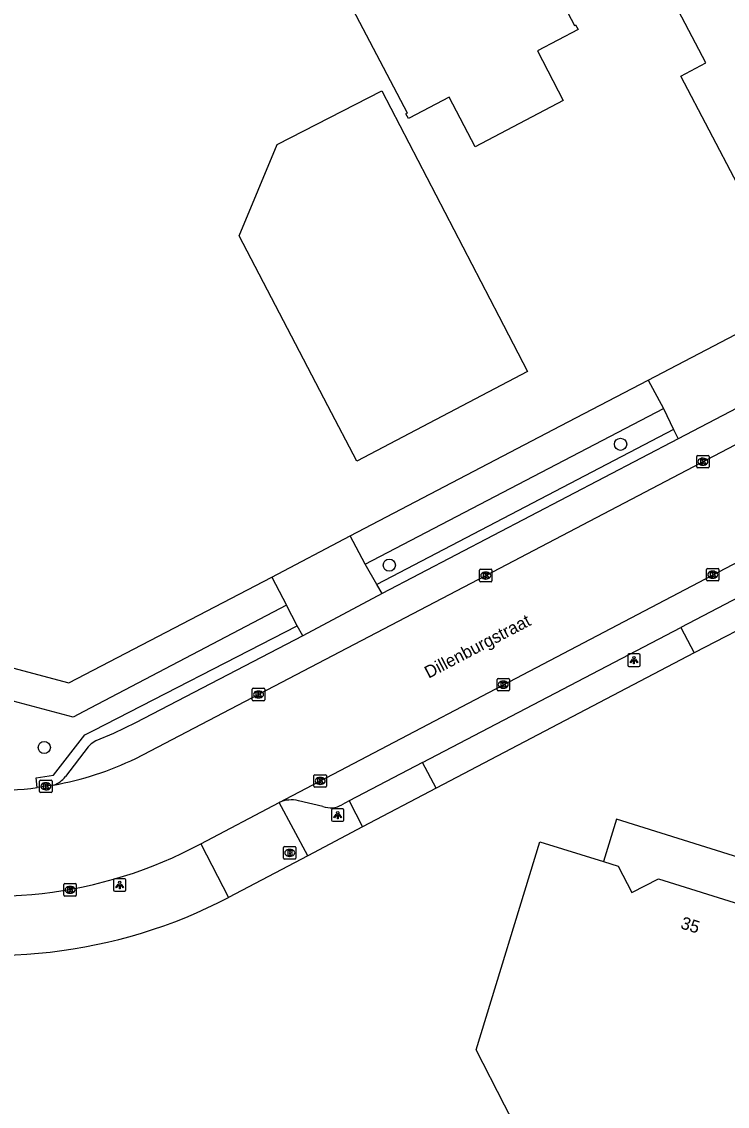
# Model space of a CAD drawing. Extents: x 157692 to 159670, y 381454 to 383289.
# Drawn here: x 158266.5 to 158323.1, y 381791.8 to 381878.9 of the extents above; entities that cross this region are included whole.
import ezdxf

# ---------------------------------------------------------------- set-up
doc = ezdxf.new("R2010")
doc.units = 0
for name, color, linetype in [('IMGEO_Boom', 7, 'Continuous'), ('IMGEO_Brandkraan', 7, 'Continuous'), ('IMGEO_Kolk', 7, 'Continuous'), ('IMGEO_Lichtpunt', 7, 'Continuous'), ('IMGEO_Openbare_ruimte_label', 7, 'Continuous'), ('IMGEO_Pand', 7, 'Continuous'), ('IMGEO_Pand_nummerreeks', 7, 'Continuous'), ('IMGEO_Pand_overbouw', 7, 'Continuous'), ('IMGEO_Rijbaan_lokaal_gesloten', 7, 'Continuous'), ('IMGEO_Rijbaan_lokaal_open', 7, 'Continuous'), ('IMGEO_Voetpad_open', 7, 'Continuous')]:
    doc.layers.add(name, color=color, linetype=linetype)

msp = doc.modelspace()

# ---------------------------------------------------------------- linework, layer by layer
at = {"layer": 'IMGEO_Boom'}
for centre in [(158314.56, 381844.953), (158295.991, 381835.243), (158268.292, 381820.598)]:
    msp.add_circle(centre, 0.489, dxfattribs=at)
at = {"layer": 'IMGEO_Brandkraan'}
for p, q in [((158287.494, 381811.713), (158287.494, 381812.565)), ((158287.569, 381812.639), (158288.421, 381812.639)), ((158288.005, 381811.859), (158287.98, 381811.859)), ((158287.982, 381812.419), (158288.007, 381812.419)), ((158288.495, 381812.565), (158288.495, 381811.713)), ((158288.421, 381811.639), (158287.569, 381811.639))]:
    msp.add_line(p, q, dxfattribs=at)
for points in [[(158287.494, 381811.713), (158287.494, 381812.565)], [(158287.569, 381812.639), (158288.421, 381812.639)], [(158287.842, 381812.339), (158287.842, 381811.939), (158288.055, 381811.939)], [(158288.073, 381812.339), (158287.842, 381812.339)], [(158288.021, 381812.258), (158287.967, 381812.258), (158287.967, 381812.182)], [(158287.967, 381812.182), (158288.02, 381812.182)], [(158288.029, 381812.106), (158287.967, 381812.106), (158287.967, 381812.025)], [(158287.967, 381812.025), (158288.029, 381812.025)], [(158288.495, 381812.565), (158288.495, 381811.713)], [(158288.421, 381811.639), (158287.569, 381811.639)]]:
    msp.add_lwpolyline(points, dxfattribs=at)
for centre, radius, start, end in [((158287.571, 381812.563), 0.0765, 91.55205, 178.44795), ((158287.571, 381812.563), 0.0765, 91.55205, 178.44795), ((158288.022, 381812.22), 0.0379, 267.82845, 90.93552), ((158288.03, 381812.065), 0.0404, 269.87594, 90.50774), ((158288.061, 381812.19), 0.251, 268.66757, 293.53466), ((158288.077, 381812.194), 0.145, 59.4692, 91.53667), ((158288.102, 381812.241), 0.0922, 285.51372, 58.15012), ((158288.107, 381812.049), 0.105, 301.31148, 78.98903), ((158288.419, 381812.563), 0.0765, 1.55205, 88.44795), ((158288.419, 381812.563), 0.0765, 1.55205, 88.44795), ((158287.571, 381811.715), 0.0765, 181.55205, 268.44795), ((158287.571, 381811.715), 0.0765, 181.55205, 268.44795), ((158288.419, 381811.715), 0.0765, 271.55205, 358.44795), ((158288.419, 381811.715), 0.0765, 271.55205, 358.44795)]:
    msp.add_arc(centre, radius, start, end, dxfattribs=at)
for centre, major_axis, ratio, start_param, end_param in [((158287.981, 381812.139), (-0.387, 0.002), 0.722429, 4.712389, 7.853982), ((158288.006, 381812.139), (-0.39, 0.002), 0.717154, 1.570796, 4.712389)]:
    msp.add_ellipse(centre, major_axis=major_axis, ratio=ratio, start_param=start_param, end_param=end_param, dxfattribs=at)
at = {"layer": 'IMGEO_Kolk'}
for p, q in [((158320.743, 381844.055), (158321.595, 381844.055)), ((158320.668, 381843.129), (158320.668, 381843.981)), ((158321.179, 381843.275), (158321.154, 381843.275)), ((158321.156, 381843.835), (158321.181, 381843.835)), ((158321.669, 381843.981), (158321.669, 381843.129)), ((158321.595, 381843.055), (158320.743, 381843.055)), ((158303.233, 381833.986), (158303.233, 381834.838)), ((158303.308, 381834.912), (158304.16, 381834.912)), ((158303.721, 381834.692), (158303.746, 381834.692)), ((158304.234, 381834.838), (158304.234, 381833.986)), ((158321.455, 381834.055), (158321.455, 381834.907)), ((158321.53, 381834.981), (158322.382, 381834.981)), ((158321.943, 381834.761), (158321.968, 381834.761)), ((158322.456, 381834.907), (158322.456, 381834.055)), ((158304.16, 381833.912), (158303.308, 381833.912)), ((158303.744, 381834.132), (158303.719, 381834.132)), ((158322.382, 381833.981), (158321.53, 381833.981)), ((158321.966, 381834.201), (158321.941, 381834.201)), ((158304.644, 381825.222), (158304.644, 381826.074)), ((158304.719, 381826.148), (158305.571, 381826.148)), ((158305.132, 381825.928), (158305.157, 381825.928)), ((158305.645, 381826.074), (158305.645, 381825.222)), ((158284.993, 381824.433), (158284.993, 381825.285)), ((158285.068, 381825.359), (158285.92, 381825.359)), ((158285.481, 381825.139), (158285.506, 381825.139)), ((158285.994, 381825.285), (158285.994, 381824.433)), ((158305.571, 381825.148), (158304.719, 381825.148)), ((158305.155, 381825.368), (158305.13, 381825.368)), ((158285.92, 381824.359), (158285.068, 381824.359)), ((158285.504, 381824.579), (158285.479, 381824.579)), ((158267.992, 381817.984), (158268.844, 381817.984)), ((158289.941, 381817.488), (158289.941, 381818.34)), ((158290.016, 381818.414), (158290.868, 381818.414)), ((158290.429, 381818.194), (158290.454, 381818.194)), ((158290.942, 381818.34), (158290.942, 381817.488)), ((158267.917, 381817.058), (158267.917, 381817.91)), ((158268.428, 381817.204), (158268.403, 381817.204)), ((158268.405, 381817.764), (158268.43, 381817.764)), ((158268.918, 381817.91), (158268.918, 381817.058)), ((158290.868, 381817.414), (158290.016, 381817.414)), ((158290.452, 381817.634), (158290.427, 381817.634)), ((158268.844, 381816.984), (158267.992, 381816.984)), ((158269.863, 381808.743), (158269.863, 381809.595)), ((158269.938, 381809.669), (158270.79, 381809.669)), ((158270.351, 381809.449), (158270.376, 381809.449)), ((158270.864, 381809.595), (158270.864, 381808.743)), ((158270.79, 381808.669), (158269.938, 381808.669)), ((158270.374, 381808.889), (158270.349, 381808.889))]:
    msp.add_line(p, q, dxfattribs=at)
for points in [[(158320.743, 381844.055), (158321.595, 381844.055)], [(158320.668, 381843.129), (158320.668, 381843.981)], [(158320.989, 381843.755), (158321.112, 381843.755), (158321.112, 381843.604), (158321.242, 381843.755), (158321.406, 381843.755), (158321.26, 381843.604), (158321.413, 381843.355), (158321.261, 381843.355), (158321.176, 381843.519), (158321.112, 381843.452), (158321.112, 381843.355), (158320.989, 381843.355), (158320.989, 381843.755)], [(158321.669, 381843.981), (158321.669, 381843.129)], [(158321.595, 381843.055), (158320.743, 381843.055)], [(158303.233, 381833.986), (158303.233, 381834.838)], [(158303.308, 381834.912), (158304.16, 381834.912)], [(158303.554, 381834.612), (158303.677, 381834.612), (158303.677, 381834.461), (158303.807, 381834.612), (158303.971, 381834.612), (158303.825, 381834.461), (158303.978, 381834.212), (158303.826, 381834.212), (158303.741, 381834.376), (158303.677, 381834.309), (158303.677, 381834.212), (158303.554, 381834.212), (158303.554, 381834.612)], [(158304.234, 381834.838), (158304.234, 381833.986)], [(158321.455, 381834.055), (158321.455, 381834.907)], [(158321.53, 381834.981), (158322.382, 381834.981)], [(158321.776, 381834.681), (158321.899, 381834.681), (158321.899, 381834.53), (158322.029, 381834.681), (158322.193, 381834.681), (158322.047, 381834.53), (158322.2, 381834.281), (158322.048, 381834.281), (158321.963, 381834.445), (158321.899, 381834.378), (158321.899, 381834.281), (158321.776, 381834.281), (158321.776, 381834.681)], [(158322.456, 381834.907), (158322.456, 381834.055)], [(158304.16, 381833.912), (158303.308, 381833.912)], [(158322.382, 381833.981), (158321.53, 381833.981)], [(158304.644, 381825.222), (158304.644, 381826.074)], [(158304.719, 381826.148), (158305.571, 381826.148)], [(158304.965, 381825.848), (158305.088, 381825.848), (158305.088, 381825.697), (158305.218, 381825.848), (158305.382, 381825.848), (158305.236, 381825.697), (158305.389, 381825.448), (158305.237, 381825.448), (158305.152, 381825.612), (158305.088, 381825.545), (158305.088, 381825.448), (158304.965, 381825.448), (158304.965, 381825.848)], [(158305.645, 381826.074), (158305.645, 381825.222)], [(158284.993, 381824.433), (158284.993, 381825.285)], [(158285.068, 381825.359), (158285.92, 381825.359)], [(158285.314, 381825.059), (158285.437, 381825.059), (158285.437, 381824.908), (158285.567, 381825.059), (158285.731, 381825.059), (158285.585, 381824.908), (158285.738, 381824.659), (158285.586, 381824.659), (158285.501, 381824.823), (158285.437, 381824.756), (158285.437, 381824.659), (158285.314, 381824.659), (158285.314, 381825.059)], [(158285.994, 381825.285), (158285.994, 381824.433)], [(158305.571, 381825.148), (158304.719, 381825.148)], [(158285.92, 381824.359), (158285.068, 381824.359)], [(158267.992, 381817.984), (158268.844, 381817.984)], [(158289.941, 381817.488), (158289.941, 381818.34)], [(158290.016, 381818.414), (158290.868, 381818.414)], [(158290.262, 381818.114), (158290.385, 381818.114), (158290.385, 381817.963), (158290.515, 381818.114), (158290.679, 381818.114), (158290.533, 381817.963), (158290.686, 381817.714), (158290.534, 381817.714), (158290.449, 381817.878), (158290.385, 381817.811), (158290.385, 381817.714), (158290.262, 381817.714), (158290.262, 381818.114)], [(158290.942, 381818.34), (158290.942, 381817.488)], [(158267.917, 381817.058), (158267.917, 381817.91)], [(158268.238, 381817.684), (158268.361, 381817.684), (158268.361, 381817.533), (158268.491, 381817.684), (158268.655, 381817.684), (158268.509, 381817.533), (158268.662, 381817.284), (158268.51, 381817.284), (158268.425, 381817.448), (158268.361, 381817.381), (158268.361, 381817.284), (158268.238, 381817.284), (158268.238, 381817.684)], [(158268.918, 381817.91), (158268.918, 381817.058)], [(158290.868, 381817.414), (158290.016, 381817.414)], [(158268.844, 381816.984), (158267.992, 381816.984)], [(158269.863, 381808.743), (158269.863, 381809.595)], [(158269.938, 381809.669), (158270.79, 381809.669)], [(158270.184, 381809.369), (158270.307, 381809.369), (158270.307, 381809.218), (158270.437, 381809.369), (158270.601, 381809.369), (158270.455, 381809.218), (158270.608, 381808.969), (158270.456, 381808.969), (158270.371, 381809.133), (158270.307, 381809.066), (158270.307, 381808.969), (158270.184, 381808.969), (158270.184, 381809.369)], [(158270.864, 381809.595), (158270.864, 381808.743)], [(158270.79, 381808.669), (158269.938, 381808.669)]]:
    msp.add_lwpolyline(points, dxfattribs=at)
for centre, start, end in [((158320.745, 381843.979), 91.55205, 178.44795), ((158320.745, 381843.979), 91.55205, 178.44795), ((158321.593, 381843.979), 1.55205, 88.44795), ((158321.593, 381843.979), 1.55205, 88.44795), ((158320.745, 381843.131), 181.55205, 268.44795), ((158320.745, 381843.131), 181.55205, 268.44795), ((158321.593, 381843.131), 271.55205, 358.44795), ((158321.593, 381843.131), 271.55205, 358.44795), ((158303.31, 381834.836), 91.55205, 178.44795), ((158303.31, 381834.836), 91.55205, 178.44795), ((158304.158, 381834.836), 1.55205, 88.44795), ((158304.158, 381834.836), 1.55205, 88.44795), ((158321.532, 381834.905), 91.55205, 178.44795), ((158321.532, 381834.905), 91.55205, 178.44795), ((158322.38, 381834.905), 1.55205, 88.44795), ((158322.38, 381834.905), 1.55205, 88.44795), ((158303.31, 381833.988), 181.55205, 268.44795), ((158303.31, 381833.988), 181.55205, 268.44795), ((158304.158, 381833.988), 271.55205, 358.44795), ((158304.158, 381833.988), 271.55205, 358.44795), ((158321.532, 381834.057), 181.55205, 268.44795), ((158321.532, 381834.057), 181.55205, 268.44795), ((158322.38, 381834.057), 271.55205, 358.44795), ((158322.38, 381834.057), 271.55205, 358.44795), ((158304.721, 381826.072), 91.55205, 178.44795), ((158304.721, 381826.072), 91.55205, 178.44795), ((158305.569, 381826.072), 1.55205, 88.44795), ((158305.569, 381826.072), 1.55205, 88.44795), ((158285.07, 381825.283), 91.55205, 178.44795), ((158285.07, 381825.283), 91.55205, 178.44795), ((158285.918, 381825.283), 1.55205, 88.44795), ((158285.918, 381825.283), 1.55205, 88.44795), ((158304.721, 381825.224), 181.55205, 268.44795), ((158304.721, 381825.224), 181.55205, 268.44795), ((158305.569, 381825.224), 271.55205, 358.44795), ((158305.569, 381825.224), 271.55205, 358.44795), ((158285.07, 381824.435), 181.55205, 268.44795), ((158285.07, 381824.435), 181.55205, 268.44795), ((158285.918, 381824.435), 271.55205, 358.44795), ((158285.918, 381824.435), 271.55205, 358.44795), ((158267.994, 381817.908), 91.55205, 178.44795), ((158267.994, 381817.908), 91.55205, 178.44795), ((158268.842, 381817.908), 1.55205, 88.44795), ((158268.842, 381817.908), 1.55205, 88.44795), ((158290.018, 381818.338), 91.55205, 178.44795), ((158290.018, 381818.338), 91.55205, 178.44795), ((158290.866, 381818.338), 1.55205, 88.44795), ((158290.866, 381818.338), 1.55205, 88.44795), ((158267.994, 381817.06), 181.55205, 268.44795), ((158267.994, 381817.06), 181.55205, 268.44795), ((158268.842, 381817.06), 271.55205, 358.44795), ((158268.842, 381817.06), 271.55205, 358.44795), ((158290.018, 381817.49), 181.55205, 268.44795), ((158290.018, 381817.49), 181.55205, 268.44795), ((158290.866, 381817.49), 271.55205, 358.44795), ((158290.866, 381817.49), 271.55205, 358.44795), ((158269.94, 381809.593), 91.55205, 178.44795), ((158269.94, 381809.593), 91.55205, 178.44795), ((158270.788, 381809.593), 1.55205, 88.44795), ((158270.788, 381809.593), 1.55205, 88.44795), ((158269.94, 381808.745), 181.55205, 268.44795), ((158269.94, 381808.745), 181.55205, 268.44795), ((158270.788, 381808.745), 271.55205, 358.44795), ((158270.788, 381808.745), 271.55205, 358.44795)]:
    msp.add_arc(centre, 0.0765, start, end, dxfattribs=at)
for centre, major_axis, ratio, start_param, end_param in [((158321.155, 381843.555), (-0.387, 0.002), 0.722429, 4.712389, 7.853982), ((158321.18, 381843.555), (-0.39, 0.002), 0.717154, 1.570796, 4.712389), ((158303.72, 381834.412), (-0.387, 0.002), 0.722429, 4.712389, 7.853982), ((158303.745, 381834.412), (-0.39, 0.002), 0.717154, 1.570796, 4.712389), ((158321.942, 381834.481), (-0.387, 0.002), 0.722429, 4.712389, 7.853982), ((158321.967, 381834.481), (-0.39, 0.002), 0.717154, 1.570796, 4.712389), ((158305.131, 381825.648), (-0.387, 0.002), 0.722429, 4.712389, 7.853982), ((158305.156, 381825.648), (-0.39, 0.002), 0.717154, 1.570796, 4.712389), ((158285.48, 381824.859), (-0.387, 0.002), 0.722429, 4.712389, 7.853982), ((158285.505, 381824.859), (-0.39, 0.002), 0.717154, 1.570796, 4.712389), ((158290.428, 381817.914), (-0.387, 0.002), 0.722429, 4.712389, 7.853982), ((158290.453, 381817.914), (-0.39, 0.002), 0.717154, 1.570796, 4.712389), ((158268.404, 381817.484), (-0.387, 0.002), 0.722429, 4.712389, 7.853982), ((158268.429, 381817.484), (-0.39, 0.002), 0.717154, 1.570796, 4.712389), ((158270.35, 381809.169), (-0.387, 0.002), 0.722429, 4.712389, 7.853982), ((158270.375, 381809.169), (-0.39, 0.002), 0.717154, 1.570796, 4.712389)]:
    msp.add_ellipse(centre, major_axis=major_axis, ratio=ratio, start_param=start_param, end_param=end_param, dxfattribs=at)
at = {"layer": 'IMGEO_Lichtpunt'}
for p, q in [((158315.132, 381828.019), (158315.132, 381827.212)), ((158315.132, 381828.019), (158315.132, 381827.212)), ((158316.034, 381828.114), (158315.226, 381828.114)), ((158316.034, 381828.114), (158315.226, 381828.114)), ((158316.128, 381827.212), (158316.128, 381828.019)), ((158316.128, 381827.212), (158316.128, 381828.019)), ((158315.226, 381827.118), (158316.034, 381827.118)), ((158315.226, 381827.118), (158316.034, 381827.118)), ((158291.355, 381815.576), (158291.355, 381814.769)), ((158291.355, 381815.576), (158291.355, 381814.769)), ((158292.257, 381815.671), (158291.449, 381815.671)), ((158292.257, 381815.671), (158291.449, 381815.671)), ((158292.351, 381814.769), (158292.351, 381815.576)), ((158292.351, 381814.769), (158292.351, 381815.576)), ((158291.449, 381814.675), (158292.257, 381814.675)), ((158291.449, 381814.675), (158292.257, 381814.675)), ((158273.851, 381809.967), (158273.851, 381809.16)), ((158273.851, 381809.967), (158273.851, 381809.16)), ((158274.753, 381810.062), (158273.945, 381810.062)), ((158274.753, 381810.062), (158273.945, 381810.062)), ((158274.847, 381809.16), (158274.847, 381809.967)), ((158274.847, 381809.16), (158274.847, 381809.967)), ((158273.945, 381809.066), (158274.753, 381809.066)), ((158273.945, 381809.066), (158274.753, 381809.066))]:
    msp.add_line(p, q, dxfattribs=at)
for points in [[(158315.506, 381827.683), (158315.545, 381827.655), (158315.357, 381827.393), (158315.319, 381827.42), (158315.506, 381827.683)], [(158315.608, 381827.635), (158315.655, 381827.635), (158315.655, 381827.313), (158315.608, 381827.313), (158315.608, 381827.635)], [(158315.718, 381827.655), (158315.756, 381827.682), (158315.943, 381827.42), (158315.904, 381827.392), (158315.718, 381827.655)], [(158291.729, 381815.24), (158291.768, 381815.212), (158291.58, 381814.95), (158291.542, 381814.977), (158291.729, 381815.24)], [(158291.831, 381815.192), (158291.878, 381815.192), (158291.878, 381814.87), (158291.831, 381814.87), (158291.831, 381815.192)], [(158291.941, 381815.212), (158291.979, 381815.239), (158292.166, 381814.977), (158292.127, 381814.949), (158291.941, 381815.212)], [(158274.225, 381809.631), (158274.264, 381809.603), (158274.076, 381809.341), (158274.038, 381809.368), (158274.225, 381809.631)], [(158274.327, 381809.583), (158274.374, 381809.583), (158274.374, 381809.261), (158274.327, 381809.261), (158274.327, 381809.583)], [(158274.437, 381809.603), (158274.475, 381809.63), (158274.662, 381809.368), (158274.623, 381809.34), (158274.437, 381809.603)]]:
    msp.add_lwpolyline(points, dxfattribs=at)
for centre in [(158315.631, 381827.817), (158291.854, 381815.374), (158274.35, 381809.765)]:
    msp.add_circle(centre, 0.0994, dxfattribs=at)
for centre, start, end in [((158315.226, 381828.019), 90, 180), ((158315.226, 381828.019), 90, 180), ((158316.034, 381828.019), 0, 90), ((158316.034, 381828.019), 0, 90), ((158315.226, 381827.212), 180, 270), ((158315.226, 381827.212), 180, 270), ((158316.034, 381827.212), 270, 0), ((158316.034, 381827.212), 270, 360), ((158291.449, 381815.576), 90, 180), ((158291.449, 381815.576), 90, 180), ((158292.257, 381815.576), 0, 90), ((158292.257, 381815.576), 0, 90), ((158291.449, 381814.769), 180, 270), ((158291.449, 381814.769), 180, 270), ((158292.257, 381814.769), 270, 0), ((158292.257, 381814.769), 270, 360), ((158273.945, 381809.967), 90, 180), ((158273.945, 381809.967), 90, 180), ((158274.753, 381809.967), 0, 90), ((158274.753, 381809.967), 0, 90), ((158273.945, 381809.16), 180, 270), ((158273.945, 381809.16), 180, 270), ((158274.753, 381809.16), 270, 0), ((158274.753, 381809.16), 270, 360)]:
    msp.add_arc(centre, 0.0946, start, end, dxfattribs=at)
at = {"layer": 'IMGEO_Pand'}
for points in [[(158333.425, 381881.552), (158340.173, 381868.726), (158333.445, 381865.185), (158333.06, 381865.918), (158331.024, 381864.849), (158331.41, 381864.114), (158326.268, 381861.408), (158323.944, 381865.836), (158319.391, 381874.508), (158321.413, 381875.583), (158309.292, 381898.698)], [(158302.242, 381895.001), (158310.853, 381878.582), (158310.95, 381878.633), (158311.145, 381878.261), (158307.877, 381876.547), (158309.962, 381872.571), (158302.877, 381868.855), (158300.792, 381872.832), (158297.598, 381871.157), (158297.524, 381871.118), (158297.329, 381871.49), (158297.444, 381871.55), (158288.402, 381888.793)], [(158304.778, 381855.232), (158307.082, 381850.794), (158293.376, 381843.602), (158291.065, 381848.036), (158283.944, 381861.695), (158286.984, 381869.041), (158295.379, 381873.333), (158304.778, 381855.232)], [(158323.96, 381772.543), (158314.42, 381790.731), (158307.678, 381787.188), (158305.25, 381791.883), (158302.954, 381796.324), (158308.072, 381813.038), (158313.184, 381811.438), (158314.365, 381811.069), (158315.463, 381808.959), (158317.611, 381810.064), (158324.541, 381807.889), (158329.01, 381810.217), (158332.059, 381811.805), (158334.384, 381807.379), (158362.682, 381753.509), (158364.526, 381750), (158365.008, 381749.083), (158325.61, 381728.481), (158323.288, 381732.91), (158314.326, 381750), (158309.193, 381759.788), (158311.05, 381765.753), (158323.96, 381772.543)]]:
    msp.add_lwpolyline(points, dxfattribs=at)
at = {"layer": 'IMGEO_Pand_overbouw'}
msp.add_lwpolyline([(158329.01, 381810.217), (158314.225, 381814.834), (158313.184, 381811.438), (158314.365, 381811.069), (158315.463, 381808.959), (158317.611, 381810.064), (158324.541, 381807.889)], close=True, dxfattribs=at)
at = {"layer": 'IMGEO_Rijbaan_lokaal_gesloten'}
for points in [[(158275.635, 381819.726), (158303.732, 381834.411), (158354.339, 381860.942), (158456.473, 381914.515), (158458.149, 381915.386), (158462.356, 381917.596)], [(158287.161, 381816.195), (158340.401, 381844.12), (158462.964, 381908.32), (158465.398, 381909.602)], [(158269.045, 381817.585), (158268.418, 381817.483), (158267.734, 381817.384)], [(158280.869, 381812.874), (158287.161, 381816.195)]]:
    msp.add_lwpolyline(points, dxfattribs=at)
for centre, radius, start, end in [((158264.757, 381841.995), 24.784, 279.96265, 296.03388), ((158264.168, 381844.191), 27.043, 259.43834, 277.57755), ((158264.153, 381843.952), 35.289, 254.62766, 298.27507)]:
    msp.add_arc(centre, radius, start, end, dxfattribs=at)
at = {"layer": 'IMGEO_Rijbaan_lokaal_open'}
for points in [[(158316.773, 381850.116), (158323.795, 381853.778)], [(158316.773, 381850.116), (158318.001, 381847.825)], [(158326.305, 381849.121), (158319.191, 381845.384)], [(158318.001, 381847.825), (158318.809, 381846.13)], [(158318.809, 381846.13), (158319.191, 381845.384)], [(158286.558, 381834.286), (158292.839, 381837.605)], [(158294.044, 381835.32), (158292.839, 381837.605)], [(158294.996, 381833.684), (158294.044, 381835.32)], [(158286.558, 381834.286), (158287.729, 381832.027)], [(158295.421, 381832.972), (158294.996, 381833.684)], [(158295.421, 381832.972), (158289.047, 381829.577)], [(158288.606, 381830.362), (158287.729, 381832.027)], [(158289.047, 381829.577), (158288.606, 381830.362)]]:
    msp.add_lwpolyline(points, dxfattribs=at)
at = {"layer": 'IMGEO_Voetpad_open'}
for points in [[(158292.839, 381837.605), (158310.343, 381846.755), (158316.773, 381850.116)], [(158294.044, 381835.32), (158318.001, 381847.825)], [(158318.809, 381846.13), (158294.996, 381833.684)], [(158319.191, 381845.384), (158295.421, 381832.972)], [(158208.31, 381842.627), (158217.316, 381839.906), (158270.263, 381825.792), (158286.558, 381834.286)], [(158325.276, 381833.312), (158319.401, 381830.234)], [(158287.729, 381832.027), (158271.462, 381823.491), (158270.606, 381823.042), (158260.949, 381825.619)], [(158326.367, 381831.251), (158320.477, 381828.192)], [(158267.734, 381817.384), (158267.631, 381818.175), (158269.03, 381818.388), (158271.535, 381821.61), (158272.252, 381821.977), (158288.606, 381830.362)], [(158298.654, 381819.389), (158319.401, 381830.234)], [(158319.401, 381830.234), (158320.477, 381828.192)], [(158289.047, 381829.577), (158275.611, 381822.585), (158273.839, 381821.727), (158272.432, 381821.141), (158272.056, 381820.902), (158271.811, 381820.664), (158269.983, 381818.259)], [(158320.477, 381828.192), (158299.749, 381817.336)], [(158298.654, 381819.389), (158292.781, 381816.313)], [(158299.749, 381817.336), (158298.654, 381819.389)], [(158299.749, 381817.336), (158293.835, 381814.232)], [(158289.45, 381811.892), (158287.161, 381816.195)], [(158290.656, 381815.851), (158288.702, 381816.326)], [(158292.781, 381816.313), (158292.185, 381815.989)], [(158292.781, 381816.313), (158293.835, 381814.232)], [(158293.835, 381814.232), (158289.45, 381811.892)], [(158280.869, 381812.874), (158283.086, 381808.549)], [(158289.45, 381811.892), (158283.086, 381808.549)]]:
    msp.add_lwpolyline(points, dxfattribs=at)
for centre, radius, start, end in [((158268.426, 381819.436), 1.951, 288.48425, 322.91403), ((158288.129, 381813.938), 2.455, 76.50262, 113.21542), ((158291.255, 381817.754), 1.995, 252.52697, 297.78755), ((158264.149, 381844.935), 41.019, 255.41399, 297.49497)]:
    msp.add_arc(centre, radius, start, end, dxfattribs=at)

# ---------------------------------------------------------------- texts
at = {"layer": 'IMGEO_Openbare_ruimte_label'}
msp.add_text('Dillenburgstraat', height=1, rotation=27.64114, dxfattribs=at).set_placement((158299.147, 381826.119))
at = {"layer": 'IMGEO_Pand_nummerreeks'}
msp.add_text('35', height=1, rotation=342.57539, dxfattribs=at).set_placement((158319.306, 381806.095))

doc.saveas('drawing.dxf')
